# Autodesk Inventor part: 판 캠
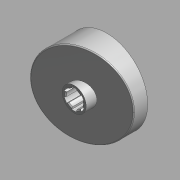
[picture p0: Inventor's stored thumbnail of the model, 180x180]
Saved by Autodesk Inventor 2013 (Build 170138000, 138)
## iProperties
Created: 2015-11
Part Number: 판 캠
Document SubType Name: 모델링
Designer: mdu
Material: 강철, 연강
Density: 7.86 g/cm^3
Mass: 682.455 g
Surface Area: 331.301 cm^2
Volume: 86.8263 cm^3
변환 표준: STEP AP214IS
파일 이름: C:\Users\SeoGD\Desktop\?쒗뿕\??stp
전처리기: Build: 253, Release: 2010 SP1 - Date: Wed 07/29/2009
전송 단위: 밀리미터
불확실성: 0.01
Author: mdu
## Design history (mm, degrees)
node "작업 평면4"
sketch "스케치1"
  geometry: C1 r 44.5 at (0, 0); 1 further point
  constraints: 1 centre point, 1 coincident
  dimensions: "d25" = 89 diameter of C1
extrude "돌출1" new body sketch "스케치1" distance "d1" = 40; taper "d2" = 0 deg
sketch "스케치2"
  geometry: L1 (-44.5, 15)-(44.5, 38.847); L2 (-44.5, 0)-(-44.5, 40) reference; L3 (-44.5, 40)-(44.5, 40) reference; L4 (44.5, 0)-(44.5, 40) reference; 1 further point
  constraints: 2 end point, 2 point on line
  dimensions: "d26" = 15 distance of L2.start L1.start; "d27" = 75 deg angle of L1 L2
extrude "돌출2" cut sketch "스케치2" stored distance "d5" = 40; taper "d6" = 0 deg
node "작업 평면1"
sketch "스케치3"
  geometry: C1 r 13 at (0, 0); 1 further point
  constraints: 1 centre point, 1 coincident
  dimensions: "d9" = 26 diameter of C1
extrude "돌출3" join sketch "스케치3" distance "d10" = 38; taper "d11" = 0 deg
hole "구멍1" diameter "d14" = 18; stored, may be unused: countersink angle "d18" = 90 deg, drill point angle "d20" = 118 deg; dims "d12" = 10, "d13" = 10, "d15" = 6, "d16" = 4, "d17" = 2, "d19" = 8
feature "쉘2" dims "d29" = 5
sketch "스케치6"
  geometry: C1 r 17.5 at (0, 0); C2 r 14 at (0, 0) reference; 1 further point
  constraints: 1 centre point, 1 coincident
  dimensions: "d28" = 35 diameter of C1
extrude "돌출4" join sketch "스케치6" stored distance "d30" = 38; taper "d31" = 0 deg
fillet "모깎기1" dims "d32" = 3
chamfer "모따기1" distance "d21" = 1; stored, may be unused: second distance "d22" = 2, angle "d23" = 45 deg
sketch "스케치7"
  geometry: L1 (-12.374, 12.374)-(-27.931, 27.931); A1 r 39.5 centre (0, 0) between (-27.931, 27.931) and (0, 39.5) reference; 2 further points
  constraints: 2 end point, 2 point on circle, 1 point on line, 1 vertical alignment, 2 other
  dimensions: "d33" = 45 deg dimension on point (0, 0) L1.start A1.end
feature "리브1" sketch "스케치7" dims "d34" = 5, "d35" = 1, "d36" = 0
fillet "모깎기2" dims "d37" = 3
sketch "스케치8"
  geometry: L1 (2.5, 10.712)-(2.5, 8.646); L2 (-2.5, 10.712)-(-2.5, 8.646); A1 r 11 centre (0, 0) between (2.5, 10.712) and (-2.5, 10.712); A2 r 9 centre (0, 0) between (2.5, 8.646) and (-2.5, 8.646) reference; 1 further point
  constraints: 4 end point, 4 point on circle, 2 parallel, 1 centre point, 1 coincident, 1 vertical
  dimensions: "d41" = 22 diameter of A1; "d42" = 5 distance between parallel lines of L1 L2
extrude "돌출5" cut sketch "스케치8" stored distance "d43" = 38; taper "d44" = 0 deg
fillet "모깎기3" dims "d48" = 1
node "솔리드1"
node "솔리드 본체"
node "곡면 본체"
pattern_circular "원형 패턴1" dims angle "d39" = 360 deg
pattern_circular "원형 패턴2" dims angle "d46" = 360 deg
node "솔리드2"
